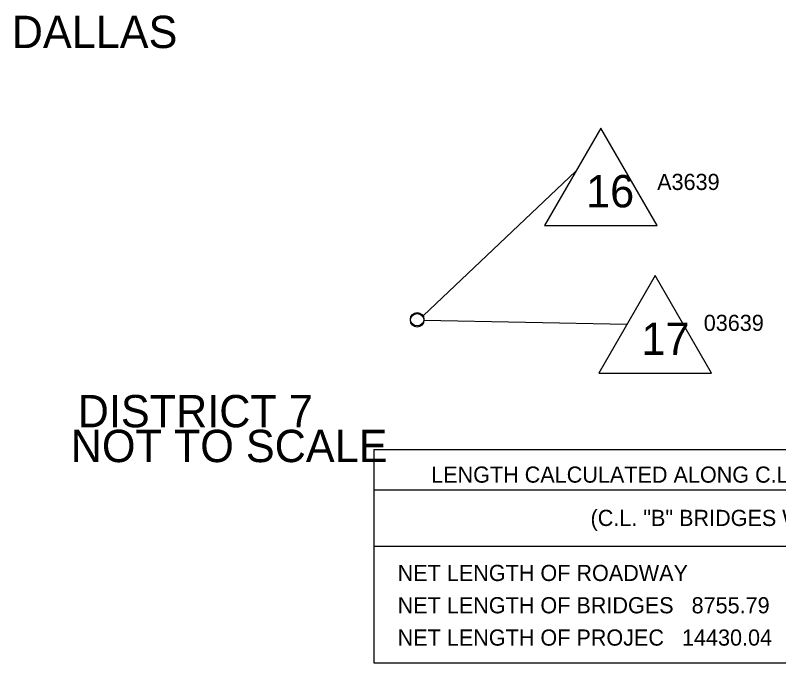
# Model space of a CAD drawing. Extents: x -35254 to 17396, y -8913 to 11592.
# Drawn here: x -2052 to 3621, y -8836 to -4026 of the extents above; entities that cross this region are included whole.
import ezdxf

# ---------------------------------------------------------------- set-up
doc = ezdxf.new("R2010")
doc.units = 0
for name, color, linetype in [('2', 7, 'Continuous'), ('3', 7, 'Continuous'), ('R_Annotation', 7, 'Continuous'), ('R_No Plot', 7, 'Continuous'), ('S_MISC_BOUNDARY', 7, 'Continuous')]:
    doc.layers.add(name, color=color, linetype=linetype)

msp = doc.modelspace()

# ---------------------------------------------------------------- linework, layer by layer
at = {"layer": 'R_Annotation'}
for p, q in [((2298.9, -4863.8), (1880.9, -5587.7)), ((2716.8, -5587.7), (2298.9, -4863.8)), ((978, -6258.5), (2114.3, -5183.5)), ((1880.9, -5587.7), (2716.8, -5587.7)), ((2703.3, -5959.6), (2285.3, -6683.5)), ((3121.2, -6683.5), (2703.3, -5959.6)), ((984.1, -6292.2), (2494.3, -6321.6)), ((2285.3, -6683.5), (3121.2, -6683.5))]:
    msp.add_line(p, q, dxfattribs=at)
for centre in [(934.1, -6284.1), (934.1, -6292.2)]:
    msp.add_circle(centre, 50, dxfattribs=at)
at = {"layer": 'S_MISC_BOUNDARY'}
for p, q in [((613.1, -7252.4), (613.1, -8835.7)), ((613.1, -7252.4), (7316.7, -7252.4)), ((613.1, -7550.6), (7316.7, -7550.6)), ((613.1, -7969.1), (7316.7, -7969.1)), ((613.1, -8835.7), (7316.7, -8835.7))]:
    msp.add_line(p, q, dxfattribs=at)

# ---------------------------------------------------------------- texts
at = {"layer": '2'}
for s, p in [('DALLAS', (-2078.8, -4269.7)), ('NOT TO SCALE', (-1640.3, -7345.5))]:
    msp.add_text(s, height=240, dxfattribs=at).set_placement(p)
at = {"layer": '3'}
for s, p in [('LENGTH CALCULATED ALONG C.L. ROADWAY AND BRIDGES', (1038, -7498.2)), ('(C.L. "B" BRIDGES WITH PAIRS)', (2222.8, -7819.9)), ('NET LENGTH OF ROADWAY', (789.2, -8228.8)), ('NET LENGTH OF BRIDGES   8755.79', (789.2, -8468.8)), ('NET LENGTH OF PROJEC   14430.04', (789.2, -8708.8))]:
    msp.add_text(s, height=120, dxfattribs=at).set_placement(p)
at = {"layer": 'R_Annotation'}
for s, p in [('16', (2190, -5453.1)), ('17', (2601, -6548.9)), ('DISTRICT 7', (-1588.6, -7086.8))]:
    msp.add_text(s, height=240, dxfattribs=at).set_placement(p)
at = {"layer": 'R_No Plot'}
for s, p in [('A3639', (2717.8, -5324)), ('03639', (3064.1, -6371.1))]:
    msp.add_text(s, height=120, dxfattribs=at).set_placement(p)

doc.saveas('drawing.dxf')
